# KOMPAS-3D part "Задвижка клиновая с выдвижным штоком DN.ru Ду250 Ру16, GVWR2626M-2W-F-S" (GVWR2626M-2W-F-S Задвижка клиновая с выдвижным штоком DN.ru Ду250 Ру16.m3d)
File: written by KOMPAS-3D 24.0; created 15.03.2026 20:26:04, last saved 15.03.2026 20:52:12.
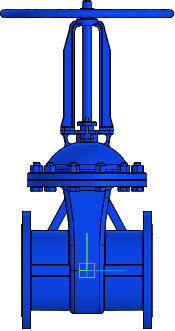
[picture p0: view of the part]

Document properties: Автор: R2D2; Полное имя файла: GVWR2626M-2W-F-S Задвижка клиновая с выдвижным штоком DN.ru Ду250 Ру16.cdw

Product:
- Part/product: Задвижка клиновая с выдвижным штоком DN.ru Ду250 Ру16  | designation GVWR2626M-2W-F-S
    Масса: 154
    Раздел спецификации: Прочие изделия
    Форматы листов документа: A2
    Примечание: D040-10506

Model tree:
1. Операция без истории:1
2. Скругление:1  (with: Ребро.Операция без истории:1)
     Радиус = 5

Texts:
  GVWR2626M-2W-F-S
